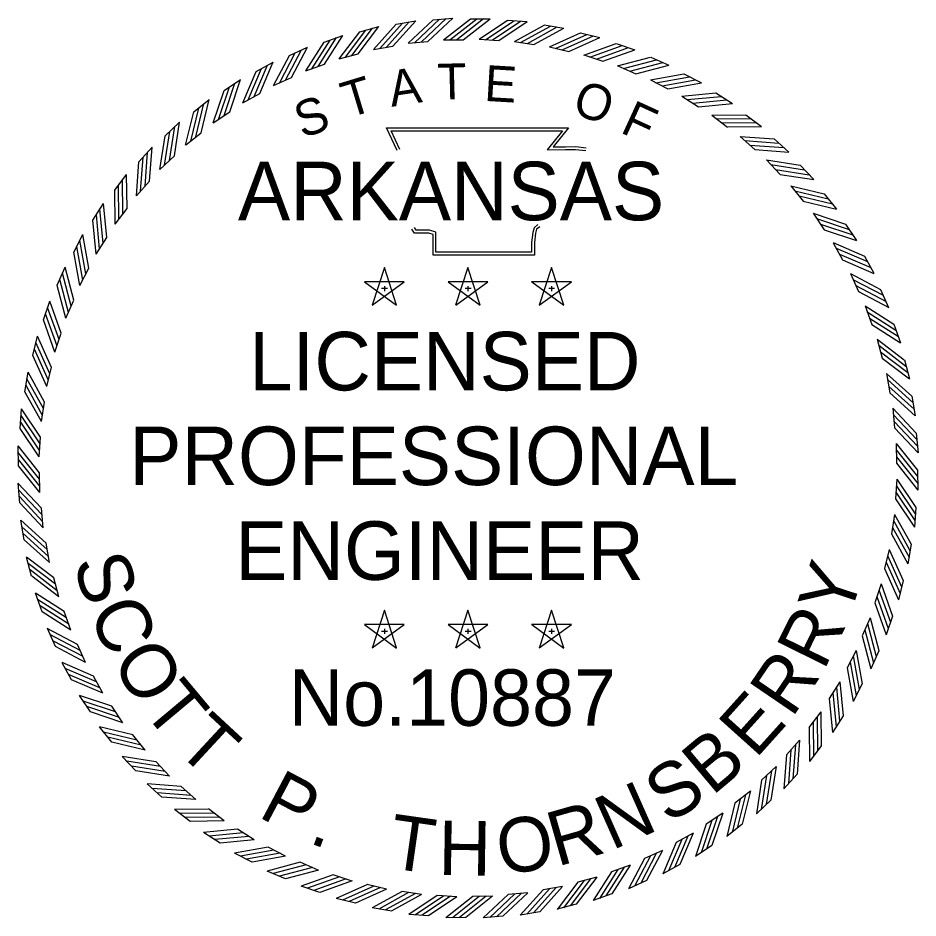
# Model space of a CAD drawing. Extents: x 166 to 3995, y -61 to 2074.
# Drawn here: x 3746.9 to 3995.3, y 283.4 to 531.8 of the extents above; entities that cross this region are included whole.
import ezdxf

# ---------------------------------------------------------------- set-up
doc = ezdxf.new("R2010")
doc.units = 0
doc.layers.add('STAMP_PP', color=7, linetype='Continuous')

msp = doc.modelspace()

# ---------------------------------------------------------------- linework, layer by layer
at = {"layer": 'STAMP_PP'}
for p, q in [((3861.5, 531.29), (3866.92, 531.79)), ((3841.27, 528.02), (3846.53, 529.41)), ((3851.32, 530.07), (3856.68, 531.02)), ((3871.81, 531.59), (3877.25, 531.59)), ((3882, 531.19), (3887.42, 530.79)), ((3892.17, 529.87), (3897.54, 529.02)), ((3831.43, 525.15), (3836.56, 526.96)), ((3902.2, 527.71), (3907.48, 526.42)), ((3854.64, 524.84), (3860.07, 525.35)), ((3864.38, 525.81), (3869.84, 525.81)), ((3874.17, 525.96), (3879.61, 525.56)), ((3883.93, 525.3), (3889.32, 524.45)), ((3912.01, 524.73), (3917.17, 523.01)), ((3821.86, 521.47), (3826.82, 523.7)), ((3835.57, 520.53), (3840.84, 521.92)), ((3845.01, 523.08), (3850.39, 524.03)), ((3893.61, 523.84), (3898.91, 522.55)), ((3812.62, 517.01), (3817.38, 519.64)), ((3903.14, 521.59), (3908.31, 519.86)), ((3921.55, 520.96), (3926.55, 518.82)), ((3826.36, 517.21), (3831.5, 519.03)), ((3912.44, 518.55), (3917.46, 516.41)), ((3803.78, 511.8), (3808.31, 514.82)), ((3817.46, 513.14), (3822.43, 515.38)), ((3921.47, 514.76), (3926.29, 512.21)), ((3930.74, 516.41), (3935.54, 513.86)), ((3808.92, 508.35), (3813.7, 510.99)), ((3930.15, 510.24), (3934.74, 507.3)), ((3939.52, 511.11), (3944.1, 508.18)), ((3795.4, 505.89), (3799.67, 509.27)), ((3800.81, 502.87), (3805.35, 505.89)), ((3938.42, 505.01), (3942.76, 501.7)), ((3947.84, 505.11), (3952.16, 501.81)), ((3787.54, 499.3), (3791.51, 503.02)), ((3793.19, 496.74), (3797.46, 500.13)), ((3946.24, 499.12), (3950.28, 495.47)), ((3955.63, 498.44), (3959.66, 494.79)), ((3780.26, 492.08), (3783.9, 496.12)), ((3786.09, 490), (3790.07, 493.73)), ((3953.54, 492.61), (3957.27, 488.63)), ((3962.84, 491.15), (3966.56, 487.18)), ((3773.59, 484.29), (3776.89, 488.62)), ((3779.57, 482.69), (3783.23, 486.74)), ((3960.28, 485.51), (3963.67, 481.24)), ((3969.43, 483.29), (3972.81, 479.03)), ((3767.59, 475.97), (3770.52, 480.56)), ((3773.68, 474.88), (3776.99, 479.21)), ((3966.41, 477.88), (3969.44, 473.34)), ((3975.35, 474.91), (3978.37, 470.39)), ((3762.29, 467.19), (3764.84, 472)), ((3768.46, 466.6), (3771.4, 471.19)), ((3971.89, 469.77), (3974.53, 465)), ((3980.55, 466.08), (3983.19, 461.32)), ((3757.74, 458), (3759.88, 463)), ((3763.93, 457.92), (3766.49, 462.74)), ((3848.03, 462.95), (3844.63, 452.51)), ((3851.42, 452.51), (3848.04, 462.96)), ((3871.11, 462.95), (3867.71, 452.51)), ((3874.5, 452.51), (3871.12, 462.96)), ((3894.19, 462.95), (3890.78, 452.51)), ((3897.58, 452.51), (3894.2, 462.96)), ((3976.69, 461.24), (3978.92, 456.26)), ((3853.52, 458.96), (3842.54, 458.97)), ((3842.54, 458.96), (3851.42, 452.5)), ((3844.64, 452.51), (3853.53, 458.96)), ((3847.25, 457.21), (3848.88, 457.21)), ((3848.04, 457.79), (3848.04, 456.41)), ((3876.6, 458.96), (3865.61, 458.97)), ((3865.62, 458.96), (3874.5, 452.5)), ((3867.72, 452.51), (3876.61, 458.96)), ((3870.33, 457.21), (3871.96, 457.21)), ((3871.12, 457.79), (3871.12, 456.41)), ((3899.68, 458.96), (3888.69, 458.97)), ((3888.7, 458.96), (3897.58, 452.5)), ((3890.8, 452.51), (3899.69, 458.96)), ((3893.41, 457.21), (3895.04, 457.21)), ((3894.2, 457.79), (3894.2, 456.41)), ((3985.01, 456.84), (3987.24, 451.88)), ((3753.96, 448.47), (3755.68, 453.63)), ((3760.14, 448.9), (3762.29, 453.91)), ((3980.76, 452.34), (3982.57, 447.2)), ((3988.69, 447.27), (3990.5, 442.14)), ((3757.11, 439.59), (3758.83, 444.77)), ((3750.99, 438.65), (3752.27, 443.94)), ((3984.08, 443.13), (3985.47, 437.86)), ((3991.57, 437.42), (3992.95, 432.16)), ((3754.85, 430.07), (3756.14, 435.37)), ((3748.83, 428.62), (3749.68, 434)), ((3986.63, 433.68), (3987.58, 428.31)), ((3993.62, 427.38), (3994.56, 422.02)), ((3753.39, 420.39), (3754.24, 425.78)), ((3747.51, 418.45), (3747.91, 423.88)), ((3988.39, 424.05), (3988.89, 418.62)), ((3752.74, 410.62), (3753.14, 416.06)), ((3994.84, 417.19), (3995.34, 411.77)), ((3747.03, 408.21), (3746.98, 413.65)), ((3989.35, 414.31), (3989.4, 408.86)), ((3752.89, 400.84), (3752.84, 406.29)), ((3995.21, 406.94), (3995.26, 401.5)), ((3747.4, 397.96), (3746.91, 403.38)), ((3989.5, 404.53), (3989.1, 399.09)), ((3753.85, 391.1), (3753.35, 396.53)), ((3994.73, 396.7), (3994.33, 391.27)), ((3748.62, 387.78), (3747.68, 393.13)), ((3988.85, 394.76), (3988, 389.37)), ((3755.61, 381.47), (3754.67, 386.84)), ((3987.39, 385.08), (3986.1, 379.79)), ((3993.41, 386.53), (3992.57, 381.15)), ((3750.67, 377.73), (3749.29, 382.99)), ((3758.16, 372.02), (3756.78, 377.29)), ((3985.13, 375.56), (3983.41, 370.39)), ((3991.26, 376.5), (3989.97, 371.21)), ((3753.55, 367.88), (3751.74, 373.01)), ((3761.48, 362.81), (3759.67, 367.96)), ((3848.03, 368.32), (3844.63, 357.88)), ((3851.42, 357.89), (3848.04, 368.34)), ((3871.11, 368.32), (3867.71, 357.88)), ((3874.5, 357.89), (3871.12, 368.34)), ((3894.19, 368.32), (3890.78, 357.88)), ((3897.58, 357.89), (3894.2, 368.34)), ((3982.1, 366.25), (3979.95, 361.24)), ((3988.28, 366.69), (3986.56, 361.52)), ((3757.23, 358.31), (3755, 363.27)), ((3853.52, 364.34), (3842.54, 364.35)), ((3842.54, 364.34), (3851.42, 357.87)), ((3844.64, 357.89), (3853.53, 364.33)), ((3848.04, 363.17), (3848.04, 361.79)), ((3876.6, 364.34), (3865.61, 364.35)), ((3865.62, 364.34), (3874.5, 357.87)), ((3867.72, 357.89), (3876.61, 364.33)), ((3871.12, 363.17), (3871.12, 361.79)), ((3899.68, 364.34), (3888.69, 364.35)), ((3888.7, 364.34), (3897.58, 357.87)), ((3890.8, 357.89), (3899.69, 364.33)), ((3894.2, 363.17), (3894.2, 361.79)), ((3847.25, 362.58), (3848.88, 362.58)), ((3870.33, 362.58), (3871.96, 362.58)), ((3893.41, 362.58), (3895.04, 362.58)), ((3765.56, 353.91), (3763.32, 358.89)), ((3978.31, 357.23), (3975.76, 352.41)), ((3984.5, 357.15), (3982.36, 352.15)), ((3761.69, 349.07), (3759.05, 353.83)), ((3770.35, 345.38), (3767.71, 350.15)), ((3973.78, 348.55), (3970.84, 343.96)), ((3979.95, 347.96), (3977.41, 343.15)), ((3766.89, 340.24), (3763.87, 344.76)), ((3775.83, 337.27), (3772.8, 341.81)), ((3968.56, 340.27), (3965.25, 335.94)), ((3974.66, 339.18), (3971.72, 334.59)), ((3772.81, 331.86), (3769.43, 336.12)), ((3781.96, 329.64), (3778.57, 333.91)), ((3962.67, 332.46), (3959.01, 328.41)), ((3968.65, 330.86), (3965.35, 326.54)), ((3779.4, 324), (3775.68, 327.97)), ((3788.7, 322.54), (3784.97, 326.52)), ((3956.15, 325.15), (3952.17, 321.42)), ((3961.99, 323.07), (3958.34, 319.03)), ((3786.61, 316.71), (3782.58, 320.36)), ((3796, 316.03), (3791.96, 319.68)), ((3949.06, 318.41), (3944.78, 315.03)), ((3954.7, 315.85), (3950.73, 312.13)), ((3794.4, 310.04), (3790.08, 313.34)), ((3803.82, 310.14), (3799.49, 313.45)), ((3941.43, 312.28), (3936.89, 309.26)), ((3946.84, 309.26), (3942.57, 305.88)), ((3802.72, 304.04), (3798.14, 306.97)), ((3812.1, 304.91), (3807.5, 307.85)), ((3933.32, 306.8), (3928.55, 304.16)), ((3938.46, 303.35), (3933.93, 300.33)), ((3811.5, 298.75), (3806.7, 301.29)), ((3820.78, 300.39), (3815.96, 302.94)), ((3924.78, 302.01), (3919.81, 299.77)), ((3829.8, 296.6), (3824.78, 298.74)), ((3929.62, 298.14), (3924.86, 295.51)), ((3820.7, 294.19), (3815.69, 296.33)), ((3915.88, 297.94), (3910.74, 296.12)), ((3839.1, 293.56), (3833.93, 295.29)), ((3906.68, 294.62), (3901.4, 293.23)), ((3920.39, 293.69), (3915.42, 291.45)), ((3830.23, 290.42), (3825.07, 292.14)), ((3848.63, 291.31), (3843.33, 292.6)), ((3858.31, 289.85), (3852.92, 290.7)), ((3897.23, 292.07), (3891.86, 291.12)), ((3840.05, 287.44), (3834.76, 288.73)), ((3868.07, 289.19), (3862.63, 289.59)), ((3877.86, 289.35), (3872.41, 289.3)), ((3887.6, 290.31), (3882.17, 289.81)), ((3910.81, 290.01), (3905.68, 288.19)), ((3850.07, 285.28), (3844.7, 286.13)), ((3900.97, 287.13), (3895.71, 285.75)), ((3860.24, 283.96), (3854.82, 284.36)), ((3870.49, 283.49), (3865.05, 283.44)), ((3880.74, 283.86), (3875.32, 283.36)), ((3890.92, 285.08), (3885.56, 284.13))]:
    msp.add_line(p, q, dxfattribs=at)
for points in [[(3860.07, 525.35), (3866.93, 531.79)], [(3840.83, 521.92), (3846.54, 529.41)], [(3845.01, 523.08), (3851.31, 530.07)], [(3846.74, 523.37), (3853.04, 530.36)], [(3848.59, 523.74), (3854.9, 530.73)], [(3850.38, 524.03), (3856.68, 531.02)], [(3854.64, 524.84), (3861.5, 531.29)], [(3856.38, 524.98), (3863.24, 531.43)], [(3858.26, 525.2), (3865.12, 531.65)], [(3864.38, 525.8), (3871.8, 531.59)], [(3866.13, 525.78), (3873.55, 531.57)], [(3868.02, 525.83), (3875.44, 531.62)], [(3869.83, 525.81), (3877.25, 531.6)], [(3874.16, 525.95), (3881.99, 531.18)], [(3875.91, 525.81), (3883.74, 531.04)], [(3877.8, 525.71), (3885.62, 530.94)], [(3879.6, 525.56), (3887.43, 530.79)], [(3883.93, 525.3), (3892.16, 529.86)], [(3885.65, 525.01), (3893.89, 529.57)], [(3887.53, 524.76), (3895.76, 529.32)], [(3831.49, 519.03), (3836.56, 526.96)], [(3835.56, 520.53), (3841.27, 528.01)], [(3837.26, 520.96), (3842.96, 528.44)], [(3839.07, 521.48), (3844.78, 528.97)], [(3889.32, 524.46), (3897.55, 529.02)], [(3893.6, 523.84), (3902.19, 527.71)], [(3895.3, 523.41), (3903.88, 527.28)], [(3897.15, 523), (3905.73, 526.87)], [(3826.35, 517.2), (3831.42, 525.14)], [(3828.01, 517.77), (3833.08, 525.71)], [(3829.78, 518.44), (3834.85, 526.38)], [(3898.91, 522.56), (3907.49, 526.43)], [(3903.13, 521.58), (3912, 524.73)], [(3819.06, 513.84), (3823.45, 522.16)], [(3820.76, 514.65), (3825.16, 522.97)], [(3822.42, 515.38), (3826.82, 523.7)], [(3904.79, 521.02), (3913.66, 524.16)], [(3906.59, 520.46), (3915.46, 523.61)], [(3908.31, 519.87), (3917.18, 523.02)], [(3813.69, 510.99), (3817.38, 519.65)], [(3817.45, 513.13), (3821.85, 521.46)], [(3912.43, 518.55), (3921.54, 520.96)], [(3914.04, 517.85), (3923.14, 520.25)], [(3915.79, 517.14), (3924.89, 519.55)], [(3808.92, 508.34), (3812.61, 517)], [(3810.46, 509.17), (3814.15, 517.83)], [(3812.09, 510.13), (3815.79, 518.79)], [(3917.45, 516.42), (3926.55, 518.82)], [(3805.34, 505.89), (3808.31, 514.83)], [(3921.46, 514.76), (3930.73, 516.4)], [(3923, 513.93), (3932.27, 515.57)], [(3924.69, 513.08), (3933.96, 514.72)], [(3800.81, 502.86), (3803.78, 511.8)], [(3802.28, 503.82), (3805.24, 512.75)], [(3803.83, 504.9), (3806.79, 513.84)], [(3926.28, 512.22), (3935.55, 513.86)], [(3930.14, 510.24), (3939.51, 511.11)], [(3931.6, 509.28), (3940.98, 510.15)], [(3794.57, 497.8), (3796.78, 506.95)], [(3796.02, 499.01), (3798.24, 508.16)], [(3797.45, 500.12), (3799.67, 509.27)], [(3933.22, 508.3), (3942.59, 509.17)], [(3934.73, 507.3), (3944.11, 508.18)], [(3793.18, 496.73), (3795.4, 505.88)], [(3938.41, 505.01), (3947.83, 505.11)], [(3790.06, 493.73), (3791.51, 503.03)], [(3939.8, 503.94), (3949.21, 504.03)], [(3941.32, 502.82), (3950.74, 502.92)], [(3787.38, 491.17), (3788.83, 500.48)], [(3788.73, 492.5), (3790.18, 501.8)], [(3851.54, 495.18), (3848.64, 501.46), (3898.82, 501.49), (3894.62, 496.22), (3898.03, 496.27), (3900.88, 496.3), (3903.72, 495.99)], [(3852.26, 495.51), (3849.88, 500.67), (3897.17, 500.69), (3892.96, 495.41), (3898.04, 495.47), (3900.84, 495.51), (3903.64, 495.2)], [(3942.75, 501.71), (3952.17, 501.81)], [(3786.09, 489.99), (3787.54, 499.29)], [(3946.23, 499.12), (3955.62, 498.44)], [(3947.52, 497.94), (3956.91, 497.26)], [(3781.99, 485.4), (3782.68, 494.79)], [(3783.22, 486.74), (3783.9, 496.13)], [(3948.95, 496.7), (3958.34, 496.02)], [(3950.28, 495.47), (3959.67, 494.79)], [(3779.57, 482.68), (3780.25, 492.07)], [(3780.76, 483.97), (3781.44, 493.36)], [(3953.53, 492.61), (3962.83, 491.15)], [(3954.72, 491.32), (3964.02, 489.87)], [(3956.04, 489.97), (3965.34, 488.52)], [(3775.87, 477.78), (3775.78, 487.19)], [(3776.99, 479.21), (3776.89, 488.62)], [(3957.27, 488.64), (3966.57, 487.18)], [(3774.76, 476.25), (3774.66, 485.66)], [(3960.27, 485.51), (3969.42, 483.29)], [(3773.68, 474.87), (3773.59, 484.28)], [(3961.35, 484.13), (3970.5, 481.91)], [(3962.56, 482.68), (3971.71, 480.46)], [(3771.39, 471.19), (3770.52, 480.56)], [(3963.67, 481.25), (3972.82, 479.03)], [(3769.42, 468.06), (3768.54, 477.43)], [(3770.4, 469.67), (3769.53, 479.05)], [(3966.41, 477.88), (3975.34, 474.92)], [(3768.46, 466.59), (3767.59, 475.97)], [(3890.41, 474.77), (3889.35, 473.91), (3888.99, 472.56), (3888.69, 469.86), (3888.69, 467.14), (3862.27, 467.14), (3862.27, 471.03), (3862.27, 472.66), (3860.46, 473.21), (3856.78, 473.21), (3856.31, 473.93)], [(3967.36, 476.42), (3976.3, 473.45)], [(3968.45, 474.87), (3977.38, 471.9)], [(3890.91, 474.15), (3890.05, 473.46), (3889.77, 472.42), (3889.48, 469.81), (3889.48, 466.35), (3861.47, 466.35), (3861.47, 471.03), (3861.47, 472.07), (3860.34, 472.42), (3856.35, 472.42), (3855.64, 473.5)], [(3969.44, 473.35), (3978.37, 470.39)], [(3765.62, 461.14), (3763.97, 470.41)], [(3766.48, 462.74), (3764.83, 472.01)], [(3971.89, 469.78), (3980.55, 466.08)], [(3763.94, 457.91), (3762.29, 467.18)], [(3764.77, 459.45), (3763.12, 468.72)], [(3972.72, 468.24), (3981.38, 464.54)], [(3973.67, 466.6), (3982.33, 462.91)], [(3974.53, 465.01), (3983.19, 461.31)], [(3762.28, 453.91), (3759.88, 463.01)], [(3761.55, 452.25), (3759.15, 461.35)], [(3976.68, 461.24), (3985, 456.85)], [(3977.38, 459.64), (3985.71, 455.24)], [(3760.14, 448.89), (3757.74, 457.99)], [(3760.85, 450.49), (3758.44, 459.6)], [(3978.19, 457.93), (3986.52, 453.54)], [(3978.92, 456.27), (3987.25, 451.88)], [(3758.83, 444.76), (3755.68, 453.63)], [(3980.75, 452.34), (3988.68, 447.27)], [(3757.68, 441.24), (3754.53, 450.11)], [(3758.24, 443.05), (3755.09, 451.92)], [(3981.32, 450.69), (3989.25, 445.62)], [(3757.11, 439.58), (3753.96, 448.46)], [(3981.99, 448.92), (3989.92, 443.85)], [(3982.58, 447.2), (3990.51, 442.13)], [(3756.14, 435.36), (3752.27, 443.94)], [(3984.07, 443.14), (3991.56, 437.43)], [(3755.29, 431.76), (3751.42, 440.34)], [(3755.69, 433.6), (3751.83, 442.19)], [(3984.5, 441.44), (3991.99, 435.73)], [(3754.86, 430.06), (3750.99, 438.64)], [(3985.02, 439.62), (3992.51, 433.91)], [(3985.47, 437.86), (3992.96, 432.16)], [(3754.24, 425.77), (3749.67, 434)], [(3986.62, 433.69), (3993.61, 427.38)], [(3753.69, 422.11), (3749.12, 430.34)], [(3753.94, 423.98), (3749.37, 432.22)], [(3986.91, 431.96), (3993.9, 425.65)], [(3987.28, 430.11), (3994.27, 423.8)], [(3753.4, 420.38), (3748.83, 428.62)], [(3987.58, 428.32), (3994.57, 422.01)], [(3753.13, 416.06), (3747.91, 423.88)], [(3988.38, 424.06), (3994.83, 417.2)], [(3752.89, 412.36), (3747.66, 420.19)], [(3752.98, 414.25), (3747.76, 422.08)], [(3988.53, 422.31), (3994.98, 415.45)], [(3988.74, 420.44), (3995.19, 413.58)], [(3752.74, 410.62), (3747.51, 418.45)], [(3988.89, 418.63), (3995.34, 411.77)], [(3752.84, 406.28), (3746.98, 413.65)], [(3989.34, 414.32), (3995.2, 406.95)], [(3989.34, 412.57), (3995.2, 405.2)], [(3752.84, 404.47), (3746.98, 411.84)], [(3752.9, 402.58), (3747.04, 409.95)], [(3989.4, 410.68), (3995.26, 403.31)], [(3752.9, 400.83), (3747.04, 408.2)], [(3989.4, 408.87), (3995.26, 401.5)], [(3753.35, 396.52), (3746.9, 403.38)], [(3989.35, 402.79), (3994.58, 394.96)], [(3989.5, 404.53), (3994.73, 396.71)], [(3753.5, 394.71), (3747.05, 401.58)], [(3989.26, 400.9), (3994.49, 393.07)], [(3753.71, 392.84), (3747.27, 399.7)], [(3753.86, 391.09), (3747.41, 397.95)], [(3989.11, 399.09), (3994.34, 391.27)], [(3754.66, 386.83), (3747.67, 393.14)], [(3988.55, 393.04), (3993.12, 384.81)], [(3988.84, 394.77), (3993.41, 386.54)], [(3754.96, 385.05), (3747.97, 391.35)], [(3988.3, 391.17), (3992.87, 382.93)], [(3755.33, 383.19), (3748.34, 389.5)], [(3755.62, 381.46), (3748.63, 387.77)], [(3988, 389.38), (3992.57, 381.15)], [(3987.38, 385.09), (3991.25, 376.51)], [(3756.77, 377.29), (3749.29, 382.99)], [(3986.95, 383.39), (3990.82, 374.81)], [(3757.22, 375.53), (3749.73, 381.24)], [(3986.55, 381.55), (3990.42, 372.97)], [(3757.74, 373.71), (3750.25, 379.42)], [(3758.17, 372.02), (3750.68, 377.72)], [(3986.1, 379.79), (3989.97, 371.21)], [(3985.13, 375.57), (3988.28, 366.69)], [(3759.67, 367.95), (3751.73, 373.02)], [(3984.56, 373.91), (3987.71, 365.04)], [(3760.25, 366.23), (3752.32, 371.3)], [(3983.41, 370.39), (3986.56, 361.52)], [(3984, 372.1), (3987.15, 363.23)], [(3760.92, 364.47), (3752.99, 369.53)], [(3761.49, 362.81), (3753.56, 367.88)], [(3982.1, 366.26), (3984.5, 357.16)], [(3763.32, 358.88), (3754.99, 363.28)], [(3980.69, 362.9), (3983.09, 353.8)], [(3981.39, 364.66), (3983.8, 355.56)], [(3764.05, 357.22), (3755.72, 361.62)], [(3979.96, 361.24), (3982.36, 352.14)], [(3764.86, 355.51), (3756.53, 359.91)], [(3765.56, 353.91), (3757.24, 358.31)], [(3977.47, 355.7), (3979.12, 346.43)], [(3978.31, 357.24), (3979.95, 347.97)], [(3767.71, 350.14), (3759.05, 353.84)], [(3976.63, 354.01), (3978.27, 344.74)], [(3768.57, 348.55), (3759.91, 352.24)], [(3769.52, 346.92), (3760.86, 350.61)], [(3975.76, 352.41), (3977.41, 343.14)], [(3770.36, 345.38), (3761.7, 349.07)], [(3973.78, 348.56), (3974.66, 339.19)], [(3971.84, 345.48), (3972.71, 336.11)], [(3972.83, 347.09), (3973.7, 337.72)], [(3772.8, 341.8), (3763.87, 344.77)], [(3773.8, 340.28), (3764.86, 343.25)], [(3970.85, 343.96), (3971.72, 334.59)], [(3774.88, 338.73), (3765.94, 341.7)], [(3775.84, 337.27), (3766.9, 340.23)], [(3967.48, 338.9), (3967.58, 329.49)], [(3968.56, 340.28), (3968.65, 330.87)], [(3778.57, 333.91), (3769.42, 336.12)], [(3965.26, 335.94), (3965.35, 326.53)], [(3966.37, 337.37), (3966.47, 327.96)], [(3779.68, 332.48), (3770.54, 334.69)], [(3780.89, 331.02), (3771.74, 333.24)], [(3781.97, 329.64), (3772.82, 331.86)], [(3961.48, 331.18), (3960.8, 321.79)], [(3962.67, 332.47), (3961.99, 323.08)], [(3784.97, 326.51), (3775.67, 327.97)], [(3959.02, 328.41), (3958.34, 319.02)], [(3960.25, 329.75), (3959.56, 320.36)], [(3786.2, 325.18), (3776.9, 326.64)], [(3787.52, 323.83), (3778.22, 325.29)], [(3788.71, 322.54), (3779.41, 324)], [(3954.87, 323.98), (3953.41, 314.68)], [(3956.15, 325.16), (3954.7, 315.86)], [(3952.18, 321.43), (3950.73, 312.12)], [(3953.52, 322.65), (3952.06, 313.35)], [(3791.96, 319.68), (3782.57, 320.36)], [(3793.29, 318.45), (3783.9, 319.13)], [(3949.06, 318.42), (3946.84, 309.27)], [(3794.72, 317.21), (3785.33, 317.9)], [(3796.01, 316.03), (3786.62, 316.71)], [(3946.22, 316.14), (3944, 306.99)], [(3947.68, 317.35), (3945.46, 308.2)], [(3799.49, 313.44), (3790.07, 313.34)], [(3944.79, 315.03), (3942.57, 305.88)], [(3800.92, 312.33), (3791.5, 312.23)], [(3802.45, 311.21), (3793.03, 311.12)], [(3939.96, 311.33), (3937, 302.4)], [(3941.43, 312.29), (3938.46, 303.36)], [(3803.83, 310.14), (3794.41, 310.04)], [(3936.9, 309.26), (3933.93, 300.32)], [(3938.41, 310.25), (3935.45, 301.32)], [(3807.51, 307.85), (3798.13, 306.97)], [(3809.02, 306.85), (3799.65, 305.98)], [(3810.64, 305.87), (3801.26, 305)], [(3931.78, 305.98), (3928.09, 297.32)], [(3933.32, 306.81), (3929.63, 298.15)], [(3812.1, 304.91), (3802.73, 304.04)], [(3928.55, 304.16), (3924.86, 295.5)], [(3930.15, 305.03), (3926.45, 296.37)], [(3815.96, 302.93), (3806.69, 301.29)], [(3817.55, 302.07), (3808.28, 300.43)], [(3819.24, 301.22), (3809.97, 299.58)], [(3923.18, 301.31), (3918.79, 292.99)], [(3924.79, 302.02), (3920.39, 293.69)], [(3820.78, 300.39), (3811.51, 298.75)], [(3824.79, 298.74), (3815.69, 296.33)], [(3919.82, 299.77), (3915.42, 291.45)], [(3921.48, 300.5), (3917.08, 292.18)], [(3826.45, 298.01), (3817.35, 295.6)], [(3828.2, 297.3), (3819.1, 294.9)], [(3829.81, 296.6), (3820.7, 294.2)], [(3910.75, 296.12), (3905.68, 288.19)], [(3912.46, 296.71), (3907.39, 288.78)], [(3914.23, 297.38), (3909.16, 289.44)], [(3915.89, 297.95), (3910.82, 290.01)], [(3833.94, 295.28), (3825.06, 292.13)], [(3835.65, 294.69), (3826.78, 291.55)], [(3837.46, 294.14), (3828.58, 290.99)], [(3839.11, 293.57), (3830.24, 290.42)], [(3901.41, 293.23), (3895.7, 285.74)], [(3903.17, 293.67), (3897.46, 286.19)], [(3904.98, 294.19), (3899.28, 286.71)], [(3906.68, 294.62), (3900.97, 287.14)], [(3843.34, 292.59), (3834.75, 288.73)], [(3845.09, 292.15), (3836.51, 288.28)], [(3846.94, 291.74), (3838.36, 287.87)], [(3848.64, 291.31), (3840.05, 287.44)], [(3852.93, 290.69), (3844.69, 286.13)], [(3891.86, 291.12), (3885.56, 284.13)], [(3893.65, 291.42), (3887.35, 284.43)], [(3895.5, 291.79), (3889.2, 284.79)], [(3897.23, 292.07), (3890.93, 285.08)], [(3854.71, 290.39), (3846.48, 285.83)], [(3856.59, 290.14), (3848.35, 285.58)], [(3858.31, 289.85), (3850.08, 285.29)], [(3862.64, 289.59), (3854.81, 284.36)], [(3864.45, 289.44), (3856.62, 284.21)], [(3866.33, 289.34), (3858.51, 284.11)], [(3868.08, 289.2), (3860.25, 283.97)], [(3872.41, 289.29), (3865.04, 283.43)], [(3874.22, 289.29), (3866.85, 283.43)], [(3876.11, 289.35), (3868.74, 283.49)], [(3877.86, 289.35), (3870.5, 283.49)], [(3882.18, 289.8), (3875.31, 283.36)], [(3883.98, 289.95), (3877.12, 283.51)], [(3885.86, 290.17), (3879, 283.72)], [(3887.6, 290.31), (3880.74, 283.87)]]:
    msp.add_lwpolyline(points, dxfattribs=at)

# ---------------------------------------------------------------- texts
for s, height, rotation, p in [('T', 9.9, 1.4789, (3862.79, 509.23)), ('A', 9.9, 8.6788, (3850.01, 507.26)), ('E', 9.9, 356.672, (3875.46, 508.93)), ('T', 9.9, 16.9015, (3837.99, 504.12)), ('O', 9.9, 341.2218, (3899.49, 505.53)), ('S', 9.9, 19.7726, (3825.4, 498.47)), ('F', 9.9, 335.3628, (3912.83, 500.32)), ('S', 15.03, 286.9475, (3762.01, 381.63)), ('Y', 15.03, 71.7733, (3976.2, 365.59)), ('C', 15.03, 294.2435, (3766.19, 367.92)), ('R', 15.03, 63.7477, (3969.32, 351.41)), ('O', 15.03, 301.9044, (3772.42, 354.22)), ('R', 15.03, 55.7221, (3960.52, 338.32)), ('T', 15.03, 309.93, (3780.84, 340.88)), ('E', 15.03, 48.0613, (3950.5, 327.09)), ('T', 15.03, 317.226, (3790.04, 329.89)), ('B', 15.03, 40.0357, (3938.49, 316.87)), ('S', 15.03, 32.7397, (3926.43, 309.12)), ('P', 15.03, 332.1828, (3812.85, 311.46)), ('N', 15.03, 23.9845, (3910.81, 301.92)), ('R', 15.03, 15.9589, (3895.68, 297.49)), ('T', 15.03, 351.882, (3848.68, 297.26)), ('O', 15.03, 7.9332, (3880.08, 295.21)), ('H', 15.03, 359.178, (3862.88, 295.24)), ('.', 15.03, 340.2084, (3826.84, 304.19))]:
    msp.add_text(s, height=height, rotation=rotation, dxfattribs=at).set_placement(p)
for s, height, p in [('ARKANSAS', 16.155, (3807.62, 475.96)), ('LICENSED', 16.155, (3810.69, 429)), ('PROFESSIONAL', 16.1547, (3777.62, 402.85)), ('ENGINEER', 16.155, (3806.85, 376.69)), ('No.10887', 15.578, (3821.62, 336.41))]:
    msp.add_text(s, height=height, dxfattribs=at).set_placement(p)

doc.saveas('drawing.dxf')
